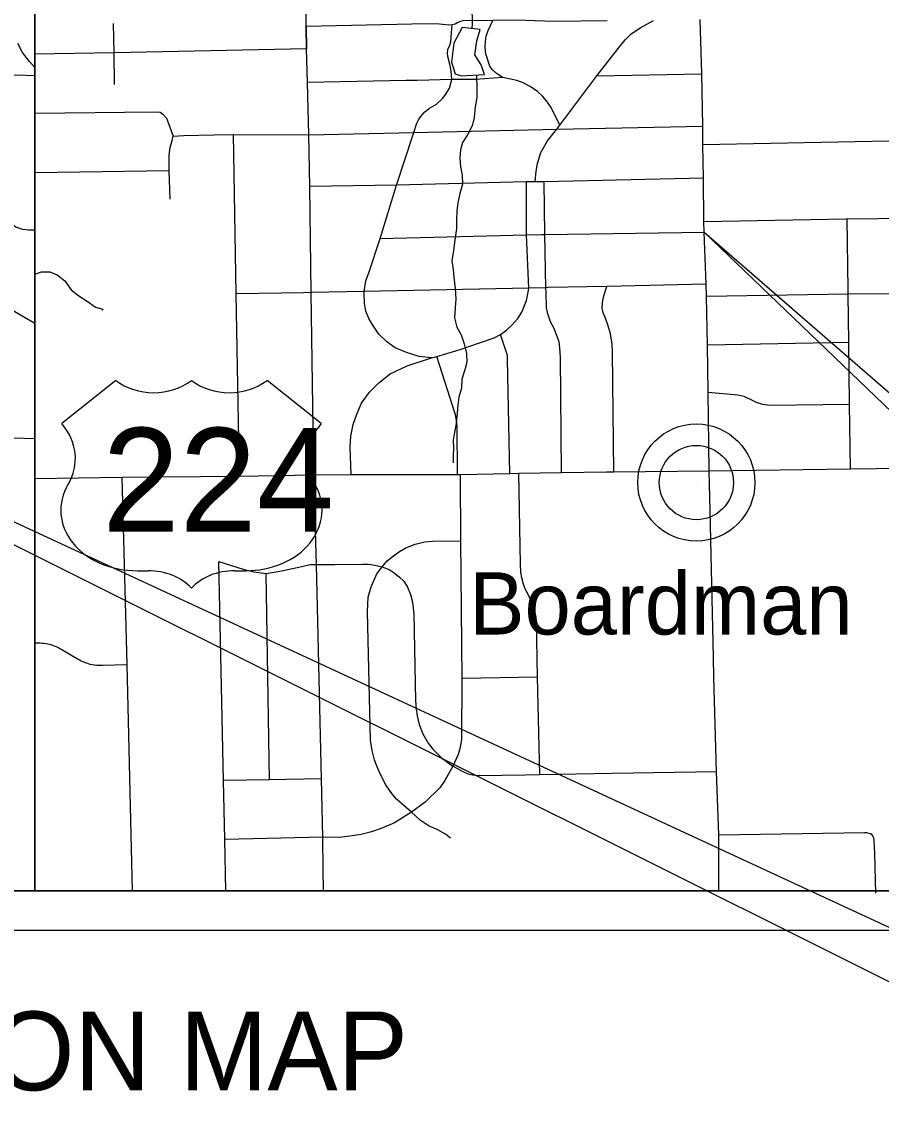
# Model space of a CAD drawing. Extents: x 25.6 to 80.6, y 0.2 to 24.5.
# Drawn here: x 40.98 to 43.163, y 13.756 to 16.537 of the extents above; entities that cross this region are included whole.
import ezdxf

# ---------------------------------------------------------------- set-up
doc = ezdxf.new("R2010")
doc.units = 0
for name, color, linetype in [('GM_X_County_Road', 7, 'Continuous'), ('GM_X_Minor_Lake', 7, 'Continuous'), ('GM_X_Minor_River', 7, 'Continuous'), ('GM_X_State_Route', 7, 'Continuous'), ('GM_X_Township_Road', 7, 'Continuous'), ('GM_X_Unincorporated', 7, 'Continuous'), ('GM_X_Unincorporated_Location', 7, 'Continuous'), ('GM_X_Unincorporated_Text', 7, 'Continuous'), ('GM_X_US_Location', 7, 'Continuous'), ('GM_X_US_Route', 7, 'Continuous'), ('GM_X_US_Shield', 7, 'Continuous'), ('SH_Data', 7, 'Continuous'), ('SH_Text', 7, 'Continuous')]:
    doc.layers.add(name, color=color, linetype=linetype)

msp = doc.modelspace()

# ---------------------------------------------------------------- linework, layer by layer
at = {"layer": 'GM_X_County_Road'}
for p, q in [((41.702, 16.5259), (41.7012, 16.6437)), ((41.7029, 16.4685), (41.702, 16.5259))]:
    msp.add_line(p, q, dxfattribs=at)
for points in [[(41.7464, 14.3303), (41.745, 14.3853), (41.7442, 14.4665), (41.7412, 14.6151), (41.7281, 15.1593), (41.7217, 15.3873), (41.7153, 15.8502), (41.7113, 16.1194), (41.7087, 16.2509), (41.7052, 16.3837), (41.7029, 16.4685)], [(41.2614, 14.3303), (41.2473, 14.9051), (41.2344, 15.3813)]]:
    msp.add_lwpolyline(points, dxfattribs=at)
at = {"layer": 'GM_X_Minor_Lake'}
for points in [[(42.0986, 16.5227), (42.0772, 16.4837), (42.0711, 16.435), (42.0806, 16.4056), (42.0966, 16.4005), (42.1549, 16.4036), (42.147, 16.4285), (42.1307, 16.4533), (42.1355, 16.4891), (42.1441, 16.5181)], [(42.1441, 16.5181), (42.0986, 16.5227)]]:
    msp.add_lwpolyline(points, dxfattribs=at)
at = {"layer": 'GM_X_Minor_River'}
for points in [[(42.0339, 16.6847), (42.0465, 16.6587), (42.0537, 16.6345), (42.0758, 16.6234), (42.095, 16.6077), (42.1157, 16.5936), (42.1221, 16.5724), (42.1239, 16.5497), (42.1242, 16.5307), (42.1235, 16.5202)], [(41.0128, 16.4218), (40.9994, 16.437), (40.9817, 16.4595), (40.97, 16.4821)], [(42.1349, 16.4025), (42.1358, 16.3668), (42.1361, 16.3456), (42.1312, 16.322), (42.1293, 16.2946), (42.1236, 16.2733), (42.1125, 16.2503), (42.0992, 16.2311), (42.0942, 16.2121), (42.093, 16.1916), (42.0941, 16.1688), (42.0989, 16.1484), (42.0993, 16.1248), (42.0928, 16.1012), (42.0871, 16.0776), (42.0852, 16.057), (42.084, 16.035), (42.0843, 16.0122), (42.0802, 15.9833), (42.0761, 15.9567), (42.0719, 15.9308), (42.0753, 15.9081), (42.0771, 15.8891), (42.0805, 15.8603), (42.0825, 15.8337), (42.0805, 15.8102), (42.0794, 15.7859), (42.0851, 15.7624), (42.096, 15.7428), (42.1039, 15.7201), (42.1096, 15.6952), (42.1106, 15.6731), (42.1049, 15.6533), (42.0977, 15.6297), (42.0965, 15.6069), (42.09, 15.584), (42.0873, 15.5642), (42.0861, 15.5445), (42.0835, 15.5171), (42.0792, 15.495), (42.0758, 15.4752), (42.0761, 15.4547), (42.0756, 15.4342), (42.0759, 15.4175)], [(41.0128, 15.8966), (41.0297, 15.9023), (41.0509, 15.9026), (41.07, 15.8953), (41.0892, 15.8796), (41.1054, 15.8571), (41.1246, 15.8414), (41.146, 15.8281), (41.1667, 15.8132), (41.1857, 15.8074), (41.1843, 15.8043)]]:
    msp.add_lwpolyline(points, dxfattribs=at)
at = {"layer": 'GM_X_State_Route'}
for p, q in [((42.7286, 15.2964), (42.7264, 15.3972)), ((42.7506, 14.3303), (42.7506, 14.3579))]:
    msp.add_line(p, q, dxfattribs=at)
for points in [[(42.7264, 15.3972), (42.7237, 15.5969), (42.7216, 15.7162), (42.7196, 15.8403), (42.7181, 15.8716), (42.7135, 16.0036), (42.7128, 16.0303), (42.7116, 16.1404), (42.7101, 16.2251), (42.7096, 16.2729), (42.707, 16.4054), (42.7033, 16.5436)], [(40.0335, 16.0001), (40.1361, 15.9961), (40.2533, 15.9918), (40.4257, 15.9853), (40.5506, 15.9807), (40.5759, 15.9793), (40.5995, 15.9774), (40.6184, 15.9749), (40.6383, 15.9717), (40.6601, 15.9661), (40.6792, 15.96), (40.6983, 15.9523), (40.7185, 15.9424), (40.7392, 15.9315), (40.857, 15.8631), (40.9869, 15.7875), (41.0128, 15.7726)], [(42.7382, 14.8731), (42.7369, 14.9233), (42.7286, 15.2964)], [(42.7506, 14.3579), (42.7506, 14.4728), (42.7443, 14.6324), (42.7382, 14.8731)]]:
    msp.add_lwpolyline(points, dxfattribs=at)
at = {"layer": 'GM_X_Township_Road'}
for p, q in [((41.702, 16.5259), (41.7029, 16.4685)), ((42.4409, 16.4002), (42.707, 16.4054)), ((43.3295, 16.2378), (42.7101, 16.2251)), ((41.0128, 16.155), (41.3545, 16.1598)), ((41.932, 16.1228), (41.7113, 16.1194)), ((42.2618, 16.1307), (41.932, 16.1228)), ((42.2836, 16.1309), (42.2618, 16.1307)), ((42.7128, 16.0303), (43.0737, 16.0369)), ((43.0757, 16.037), (43.0784, 15.8575)), ((43.0797, 15.7233), (42.7216, 15.7162)), ((41.6088, 14.6126), (41.6003, 15.1365)), ((42.0977, 14.8704), (42.2896, 14.8739)), ((42.7443, 14.6324), (42.4794, 14.6283))]:
    msp.add_line(p, q, dxfattribs=at)
for points in [[(41.2149, 16.3784), (41.2142, 16.4589), (41.2131, 16.5336)], [(42.4666, 16.5399), (42.3324, 16.5384), (42.2355, 16.5414), (42.1764, 16.5406), (42.1005, 16.5399), (42.0944, 16.5385), (42.0878, 16.5355), (42.0808, 16.5319), (42.0729, 16.5296), (42.0649, 16.5287), (42.0321, 16.5321), (41.9704, 16.5317), (41.702, 16.5259)], [(41.9729, 16.2488), (41.9754, 16.2564), (41.9833, 16.2797), (41.9873, 16.2886), (41.9928, 16.2962), (42.0036, 16.3091), (42.0157, 16.318), (42.0329, 16.3286), (42.0484, 16.3426), (42.0573, 16.3536), (42.0662, 16.3687), (42.0725, 16.3909), (42.071, 16.4128), (42.0676, 16.4302), (42.0623, 16.4496), (42.0611, 16.4575), (42.0624, 16.467), (42.0676, 16.4785), (42.0694, 16.4863), (42.0717, 16.5098), (42.0729, 16.5296)], [(42.201, 16.396), (42.1846, 16.4073), (42.1745, 16.4162), (42.1692, 16.4249), (42.159, 16.4562), (42.1571, 16.4721), (42.1581, 16.4876), (42.1599, 16.5009), (42.1649, 16.5158), (42.1764, 16.5406)], [(42.2836, 16.1309), (42.2862, 16.1583), (42.29, 16.1781), (42.2986, 16.2052), (42.3156, 16.235), (42.3389, 16.2649), (42.347, 16.2752), (42.4409, 16.4002), (42.495, 16.4698), (42.5125, 16.4919), (42.5267, 16.5065), (42.5505, 16.5222), (42.585, 16.5412)], [(41.7029, 16.4685), (41.2142, 16.4589), (41.0128, 16.4557)], [(40.927, 16.1046), (40.9274, 16.1167), (40.9289, 16.1495), (40.9264, 16.1714), (40.9224, 16.1873), (40.912, 16.2126), (40.9021, 16.2359), (40.8966, 16.2548), (40.8916, 16.2771), (40.8941, 16.3312), (40.8976, 16.3501), (40.9035, 16.365), (40.9145, 16.3804), (40.9269, 16.3913), (40.9448, 16.4002), (40.9646, 16.4027), (41.0128, 16.4013)], [(41.9841, 16.3888), (41.9566, 16.3882), (41.7052, 16.3837)], [(42.347, 16.2752), (42.325, 16.3201), (42.3131, 16.3365), (42.3027, 16.3488), (42.2896, 16.3608), (42.2711, 16.3733), (42.2533, 16.3822), (42.237, 16.3886), (42.2139, 16.3939), (42.201, 16.396), (42.1321, 16.3907), (42.0725, 16.3909), (41.9841, 16.3888)], [(41.0128, 16.3051), (41.3167, 16.3091), (41.3309, 16.3077), (41.3385, 16.3033), (41.3471, 16.2929), (41.364, 16.2472), (41.3916, 16.2491), (41.4684, 16.2503)], [(41.4684, 16.2503), (41.5177, 16.251), (41.7087, 16.2509), (41.9754, 16.2564), (42.3389, 16.2649), (42.7096, 16.2729)], [(41.357, 16.0874), (41.3545, 16.1598), (41.3545, 16.1985), (41.3568, 16.2187), (41.362, 16.2358), (41.364, 16.2472)], [(41.5327, 15.3834), (41.5248, 15.8468), (41.5177, 16.251)], [(41.8495, 15.8463), (41.8494, 15.8527), (41.8534, 15.8794), (41.8621, 15.9027), (41.8898, 15.987), (41.932, 16.1228), (41.9729, 16.2488)], [(42.7116, 16.1404), (42.3065, 16.1308), (42.2836, 16.1309)], [(41.0128, 16.0085), (40.9969, 16.0085), (40.9825, 16.01), (40.9646, 16.0164), (40.9477, 16.0294), (40.9363, 16.0448), (40.9294, 16.0582), (40.9259, 16.0745), (40.9264, 16.0884), (40.927, 16.1046)], [(42.2659, 15.8505), (42.2679, 15.8607), (42.2622, 15.9963), (42.2618, 16.1307)], [(42.3117, 15.8499), (42.3113, 15.8623), (42.3089, 15.9972), (42.3065, 16.1308)], [(43.0737, 16.0369), (43.0757, 16.037), (43.2341, 16.039)], [(41.8898, 15.987), (42.2622, 15.9963), (42.3011, 15.9971)], [(42.3011, 15.9971), (42.3089, 15.9972), (42.7135, 16.0036)], [(41.0128, 15.4788), (40.9338, 15.4806), (40.5985, 15.4883), (40.6069, 15.7018), (40.611, 15.823), (40.6184, 15.9749)], [(42.3173, 15.8624), (42.3113, 15.8623), (42.2679, 15.8607), (41.8494, 15.8527), (41.7153, 15.8502)], [(42.7181, 15.8716), (42.4663, 15.8652), (42.3173, 15.8624)], [(42.484, 15.3949), (42.4804, 15.6982), (42.4792, 15.7189), (42.475, 15.7453), (42.4696, 15.7651), (42.4624, 15.7849), (42.457, 15.7987), (42.4543, 15.8107), (42.4552, 15.8245), (42.4585, 15.8418), (42.4663, 15.8652)], [(43.4157, 15.8771), (43.2803, 15.8476), (43.2569, 15.8464), (43.0785, 15.8456), (42.7196, 15.8403)], [(43.0784, 15.8575), (43.0785, 15.8456), (43.0797, 15.7233), (43.082, 15.5669), (43.0843, 15.4023)], [(41.7153, 15.8502), (41.6952, 15.8493), (41.5248, 15.8468)], [(41.8163, 15.3876), (41.8144, 15.4577), (41.8159, 15.4853), (41.8212, 15.5145), (41.8311, 15.5413), (41.8432, 15.5686), (41.8633, 15.597), (41.8867, 15.6205), (41.9155, 15.6432), (41.9591, 15.6636), (42.0204, 15.6841), (42.034, 15.6879), (42.0931, 15.7053), (42.1427, 15.722), (42.1802, 15.7348), (42.1957, 15.7435), (42.2114, 15.7541), (42.2247, 15.767), (42.2398, 15.7844), (42.2499, 15.7998), (42.262, 15.8301), (42.2659, 15.8505)], [(42.0204, 15.6841), (41.9897, 15.6879), (41.9568, 15.6974), (41.9284, 15.7098), (41.9068, 15.7249), (41.8866, 15.7441), (41.8696, 15.7696), (41.8614, 15.7841), (41.8542, 15.8026), (41.85, 15.8229), (41.8495, 15.8463)], [(42.3506, 15.3928), (42.3482, 15.686), (42.347, 15.7084), (42.3446, 15.7246), (42.3386, 15.7423), (42.3323, 15.7585), (42.3233, 15.7756), (42.3161, 15.796), (42.3131, 15.811), (42.3117, 15.8499)], [(42.2194, 15.3908), (42.2141, 15.6809), (42.2135, 15.6898), (42.2071, 15.7106), (42.1957, 15.7435)], [(42.0865, 15.3882), (42.0855, 15.5112), (42.084, 15.5252), (42.0814, 15.5398), (42.034, 15.6879)], [(42.7237, 15.5969), (42.7992, 15.5903), (42.8141, 15.5869), (42.8373, 15.5759), (42.847, 15.571), (42.8613, 15.5662), (42.8813, 15.5637), (43.082, 15.5669)], [(42.0935, 15.3882), (42.0943, 15.2195), (42.0977, 14.8704), (42.0966, 14.7156), (42.0936, 14.6947), (42.0883, 14.6764), (42.0751, 14.647), (42.0547, 14.6104), (42.0414, 14.592), (42.0045, 14.5559), (41.9694, 14.53), (41.9269, 14.5036), (41.8927, 14.4885), (41.8678, 14.4801), (41.8419, 14.4735), (41.8135, 14.4691), (41.7859, 14.4664), (41.7442, 14.4665), (41.4952, 14.4605)], [(42.2961, 14.6254), (42.2896, 14.8739), (42.2873, 15.0146), (42.2863, 15.0255), (42.2832, 15.0412), (42.2792, 15.0537), (42.2731, 15.069), (42.2635, 15.088), (42.2576, 15.0994), (42.2542, 15.1097), (42.2502, 15.1253), (42.2478, 15.1387), (42.2466, 15.1604), (42.2427, 15.391)], [(41.4801, 15.1669), (41.5424, 15.1477), (41.5696, 15.1409), (41.6003, 15.1365), (41.6155, 15.1387), (41.6395, 15.1433), (41.691, 15.1545), (41.7127, 15.159), (41.7281, 15.1593), (41.7747, 15.1597), (41.8461, 15.1603), (41.8608, 15.1598), (41.877, 15.1577), (41.8951, 15.1536), (41.9081, 15.1684), (41.9237, 15.1815), (41.9397, 15.1923), (41.9556, 15.2019), (41.979, 15.2112), (42.0041, 15.2167), (42.0229, 15.2189), (42.0943, 15.2195)], [(41.4985, 14.3303), (41.4952, 14.4605), (41.4926, 14.6104), (41.4801, 15.1669)], [(42.0689, 14.4639), (42.0563, 14.4746), (42.0352, 14.4863), (42.0144, 14.4951), (41.9915, 14.5099), (41.9694, 14.53), (41.9313, 14.5634), (41.922, 14.5744), (41.9038, 14.6007), (41.8875, 14.6335), (41.8814, 14.6468), (41.8761, 14.6636), (41.87, 14.6868), (41.8653, 14.713), (41.8577, 15.0391), (41.8596, 15.0761), (41.8671, 15.1024), (41.882, 15.1352), (41.8951, 15.1536)], [(41.8951, 15.1536), (41.9132, 15.1466), (41.926, 15.1378), (41.9396, 15.1271), (41.95, 15.1166), (41.9597, 15.1019), (41.9675, 15.0832), (41.9727, 15.0636), (41.9759, 15.0333), (41.9799, 14.8135), (41.9814, 14.7916), (41.9839, 14.775), (41.9894, 14.7533), (41.9988, 14.7289), (42.0121, 14.7055), (42.0239, 14.6905), (42.0464, 14.668), (42.0751, 14.647)], [(41.0128, 14.9601), (41.0214, 14.9601), (41.0263, 14.9601), (41.0315, 14.9598), (41.0364, 14.9593), (41.0407, 14.9586), (41.046, 14.9576), (41.0505, 14.9566), (41.0552, 14.9553), (41.062, 14.953), (41.0712, 14.9491), (41.0768, 14.9462), (41.0816, 14.9434), (41.1228, 14.9192), (41.126, 14.9173), (41.1304, 14.915), (41.135, 14.9128), (41.1397, 14.9108), (41.1439, 14.9093), (41.1483, 14.9079), (41.153, 14.9065), (41.1584, 14.9053), (41.1642, 14.9042), (41.1704, 14.9035), (41.1849, 14.9034), (41.2473, 14.9051)], [(42.2585, 14.6247), (42.142, 14.6226), (42.1252, 14.6241), (42.1141, 14.6272), (42.1028, 14.6316), (42.0751, 14.647)], [(41.7412, 14.6151), (41.6088, 14.6126), (41.4926, 14.6104)], [(42.4794, 14.6283), (42.2961, 14.6254), (42.2585, 14.6247)], [(42.7506, 14.4728), (43.1205, 14.4791), (43.1254, 14.4786), (43.1315, 14.4772), (43.1355, 14.4757)], [(43.1496, 14.3246), (43.1467, 14.4243), (43.1452, 14.4581), (43.1441, 14.4645), (43.1418, 14.47), (43.1392, 14.4732), (43.1371, 14.4749), (43.1355, 14.4757)]]:
    msp.add_lwpolyline(points, dxfattribs=at)
at = {"layer": 'GM_X_Unincorporated'}
for radius in [0.1488, 0.0943]:
    msp.add_circle((42.6935, 15.3674), radius, dxfattribs=at)
at = {"layer": 'GM_X_Unincorporated_Location'}
msp.add_line((42.6935, 15.3674), (42.6935, 15.3674), dxfattribs=at)
at = {"layer": 'GM_X_US_Route'}
for points in [[(41.0128, 15.3776), (41.2344, 15.3813), (41.5327, 15.3834), (41.7217, 15.3873), (41.8163, 15.3876), (42.0865, 15.3882), (42.0935, 15.3882), (42.2194, 15.3908), (42.2427, 15.391), (42.3506, 15.3928), (42.4649, 15.3946)], [(42.4649, 15.3946), (42.484, 15.3949), (42.7264, 15.3972)], [(42.7264, 15.3972), (43.0843, 15.4023), (43.2853, 15.4047), (43.3867, 15.4055), (43.5241, 15.4082)]]:
    msp.add_lwpolyline(points, dxfattribs=at)
at = {"layer": 'GM_X_US_Shield'}
for p, q in [((41.2184, 15.6269), (41.0811, 15.517)), ((41.7403, 15.517), (41.603, 15.6269)), ((41.2734, 15.1435), (41.3008, 15.1435)), ((41.5206, 15.1435), (41.548, 15.1435))]:
    msp.add_line(p, q, dxfattribs=at)
for centre, major_axis, start_param, end_param in [((41.3146, 15.7054), (-0.1373, 0), 0.795399, 2.346194), ((41.5068, 15.7054), (-0.1373, 0), 0.795399, 2.346194), ((40.9236, 15.4288), (0.1923, 0), 5.838949, 6.894067), ((41.8978, 15.4288), (-0.1923, 0), 5.672304, 6.727422), ((41.2712, 15.2973), (0.1923, 0), 2.702327, 4.723529), ((41.5502, 15.2973), (-0.1923, 0), 1.559657, 3.580859), ((41.3008, 15.0336), (-0.1373, 0), 3.785094, 4.712389), ((41.5206, 15.0336), (-0.1373, 0), 4.712389, 5.639684)]:
    msp.add_ellipse(centre, major_axis=major_axis, ratio=0.8, start_param=start_param, end_param=end_param, dxfattribs=at)
at = {"layer": 'SH_Data'}
for p, q in [((41.0128, 21.1303), (41.0128, 14.3303)), ((37.6128, 14.3303), (44.4128, 14.3303)), ((37.6128, 14.3303), (44.4128, 14.3303)), ((37.5128, 14.2303), (47.9128, 14.2303))]:
    msp.add_line(p, q, dxfattribs=at)
at = {"layer": 'SH_Text'}
for points in [[(37.6128, 21.1303), (44.4128, 21.1303), (44.4128, 14.3303), (37.6128, 14.3303)], [(37.6128, 21.1303), (44.4128, 21.1303), (44.4128, 14.3303), (37.6128, 14.3303)], [(37.6128, 14.3303), (41.0128, 14.3303), (41.0128, 17.7303), (37.6128, 17.7303)], [(37.6128, 14.3303), (41.0128, 14.3303), (41.0128, 17.7303), (37.6128, 17.7303)], [(41.0128, 14.3303), (44.4128, 14.3303), (44.4128, 17.7303), (41.0128, 17.7303)], [(41.0128, 14.3303), (44.4128, 14.3303), (44.4128, 17.7303), (41.0128, 17.7303)], [(44.9027, 13.4418), (44.9027, 13.2418), (39.3128, 16.0303)], [(44.8898, 14.1167), (44.8898, 13.9167), (42.7135, 16.0036)]]:
    msp.add_lwpolyline(points, close=True, dxfattribs=at)

# ---------------------------------------------------------------- texts
at = {"layer": 'GM_X_Unincorporated_Text'}
msp.add_text('Boardman', height=0.15795, rotation=0, dxfattribs=at).set_placement((42.116, 14.9815))
at = {"layer": 'GM_X_US_Location'}
for s in ['0', '/']:
    msp.add_text(s, height=0.000379, dxfattribs=at).set_placement((41.3125, 15.3755))
msp.add_text('224', height=0.000379, rotation=0, dxfattribs=at).set_placement((41.196, 15.2971))
at = {"layer": 'GM_X_US_Shield'}
msp.add_text('224', height=0.26367, dxfattribs=at).set_placement((41.1844, 15.2424))
at = {"layer": 'SH_Text'}
msp.add_text('LOCATION MAP', height=0.2, dxfattribs=at).set_placement((39.9397, 13.824))

doc.saveas('drawing.dxf')
